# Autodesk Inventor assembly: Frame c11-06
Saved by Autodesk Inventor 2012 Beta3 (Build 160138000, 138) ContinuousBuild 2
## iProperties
Created: 2011-01
Part Number: Frame c11-06
Document SubType Name: Assembly
Designer: Beta-8540w
Author: Beta-8540w
_FrameDoc: Frame Assembly
_Version: 15.0.0
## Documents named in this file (20)
- C:\Inventor 2012 Essentials\Assemblies\Chapter 11\Frame\Frame c11-06.iam
- C:\Inventor 2012 Essentials\Assemblies\Chapter 11\Frame\Skeleton-c11-06.ipt
- C:\Inventor 2012 Essentials\Assemblies\Chapter 11\Frame\ANSI L 1.5 x 1.5 x 3_16 00000001.ipt
- ANSI L 1.5 x 1.5 x 3_16 00000001.ipt
- C:\Inventor 2012 Essentials\Assemblies\Chapter 11\Frame\ANSI L 1.5 x 1.5 x 3_16 00000002.ipt
- ANSI L 1.5 x 1.5 x 3_16 00000002.ipt
- C:\Inventor 2012 Essentials\Assemblies\Chapter 11\Frame\ANSI 3x3x3_16 00000025.ipt
- ANSI 3x3x3_16 00000025.ipt
- C:\Inventor 2012 Essentials\Assemblies\Chapter 11\Frame\ANSI 3x3x3_16 00000026.ipt
- ANSI 3x3x3_16 00000026.ipt
- C:\Inventor 2012 Essentials\Assemblies\Chapter 11\Frame\ANSI 3x3x3_16 00000027.ipt
- ANSI 3x3x3_16 00000027.ipt
- C:\Inventor 2012 Essentials\Assemblies\Chapter 11\Frame\ANSI 3x3x3_16 00000028.ipt
- ANSI 3x3x3_16 00000028.ipt
- C:\Inventor 2012 Essentials\Assemblies\Chapter 11\Frame\ANSI 3x3x3_16 00000029.ipt
- ANSI 3x3x3_16 00000029.ipt
- C:\Inventor 2012 Essentials\Assemblies\Chapter 11\Frame\ANSI 2 1_4x5_16 00000030.ipt
- ANSI 2 1_4x5_16 00000030.ipt
- C:\Inventor 2012 Essentials\Assemblies\Chapter 11\Frame\ANSI 3x3x3_16 00000031.ipt
- ANSI 3x3x3_16 00000031.ipt
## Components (10 placed, 10 different names)
1. Frame Reference Model
2. ANSI L 1.5 x 1.5 x 3_16 00000001:1
3. ANSI L 1.5 x 1.5 x 3_16 00000002:1
4. ANSI 3x3x3_16 00000025:1
5. ANSI 3x3x3_16 00000026:1
6. ANSI 3x3x3_16 00000027:1
7. ANSI 3x3x3_16 00000028:1
8. ANSI 3x3x3_16 00000029:1
9. ANSI 2 1_4x5_16 00000030:1
10. ANSI 3x3x3_16 00000031:1
